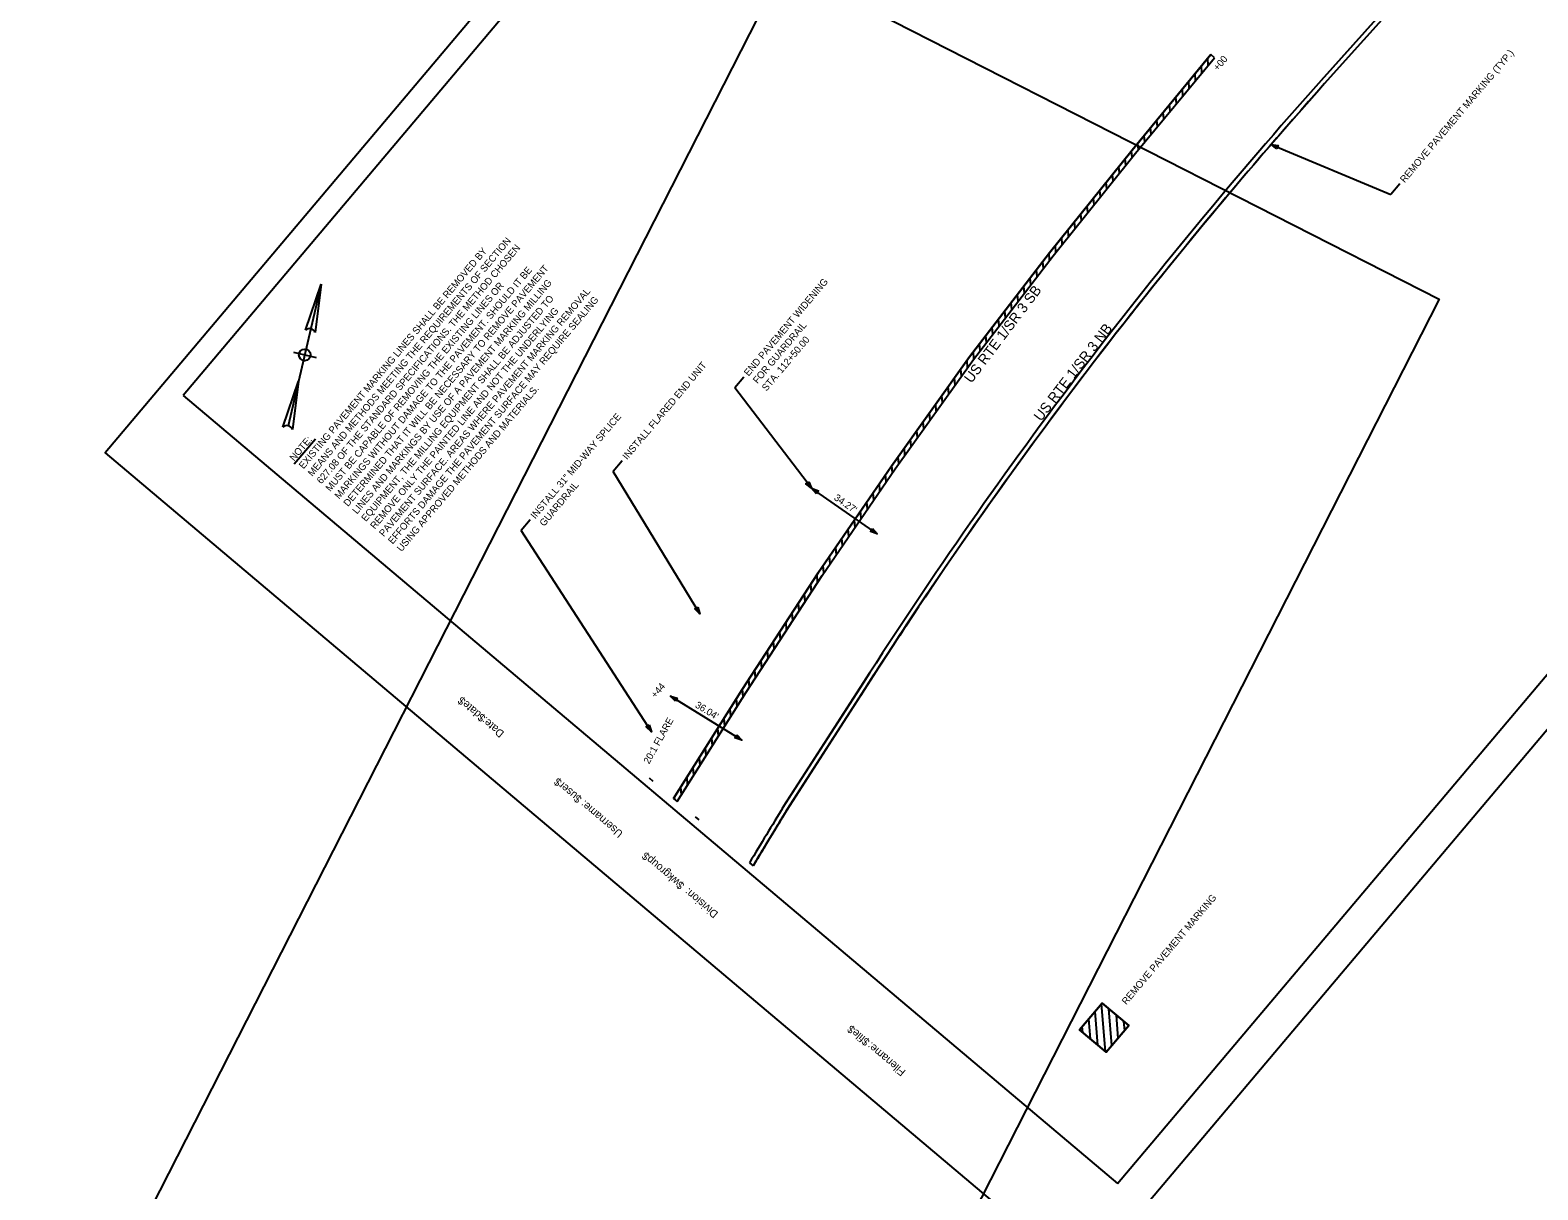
# Model space of a CAD drawing. Extents: x 1667331 to 1668332, y 338257 to 339476.
# Drawn here: x 1667331 to 1667979, y 338510 to 339008 of the extents above; entities that cross this region are included whole.
import ezdxf

# ---------------------------------------------------------------- set-up
doc = ezdxf.new("R2010")
doc.units = 0
for name, color, linetype in [('ANNOTATION', 7, 'Continuous'), ('BORDER', 7, 'Continuous'), ('CLIPS', 7, 'Continuous'), ('DIMENSIONS', 7, 'Continuous'), ('H_V CONTROLS', 7, 'Continuous'), ('PATTERNING', 7, 'Continuous'), ('PLOT BOUNDARY', 7, 'Continuous'), ('SHADING', 7, 'Continuous')]:
    doc.layers.add(name, color=color, linetype=linetype)

msp = doc.modelspace()

# ---------------------------------------------------------------- linework, layer by layer
at = {"layer": 'ANNOTATION'}
for p, q in [((1667864.55, 338958.88), (1667915.92, 338937.4)), ((1667919.79, 338941.99), (1667915.92, 338937.4)), ((1667919.79, 338941.99), (1667915.92, 338937.4)), ((1667919.79, 338941.99), (1667915.92, 338937.4)), ((1667637.98, 338858.92), (1667634.12, 338854.33)), ((1667667.17, 338811.15), (1667634.12, 338854.33)), ((1667444.93, 338821.68), (1667454.01, 338832.44)), ((1667585.82, 338823.01), (1667581.95, 338818.43)), ((1667619.21, 338757.17), (1667581.95, 338818.43)), ((1667546.32, 338797.61), (1667542.45, 338793.02)), ((1667598.39, 338706.56), (1667542.45, 338793.02))]:
    msp.add_line(p, q, dxfattribs=at)
for points in [[(1667867.03, 338957.03), (1667864.55, 338958.88), (1667867.61, 338958.41)], [(1667665.94, 338813.99), (1667667.17, 338811.15), (1667664.75, 338813.08)], [(1667665.94, 338813.99), (1667667.17, 338811.15), (1667664.75, 338813.08)], [(1667618.3, 338760.12), (1667619.21, 338757.17), (1667617.01, 338759.34)], [(1667597.39, 338709.48), (1667598.39, 338706.56), (1667596.13, 338708.67)]]:
    msp.add_lwpolyline(points, close=True, dxfattribs=at)
at = {"layer": 'BORDER'}
for p, q in [((1667913.08, 339462.54), (1667397.25, 338851.05)), ((1667798.54, 338512.53), (1668314.37, 339124.02)), ((1667397.25, 338851.05), (1667798.54, 338512.53))]:
    msp.add_line(p, q, dxfattribs=at)
at = {"layer": 'CLIPS'}
msp.add_lwpolyline([(1667331.49, 338399.89), (1667655.46, 339035.73), (1667936.78, 338892.39), (1667612.81, 338256.55)], close=True, dxfattribs=at)
at = {"layer": 'DIMENSIONS'}
for p, q in [((1667695.29, 338791.56), (1667667.17, 338811.15)), ((1667695.29, 338791.56), (1667667.17, 338811.15)), ((1667637.16, 338702.99), (1667606.49, 338721.92))]:
    msp.add_line(p, q, dxfattribs=at)
for points in [[(1667669.2, 338808.82), (1667667.17, 338811.15), (1667670.06, 338810.05)], [(1667669.2, 338808.82), (1667667.17, 338811.15), (1667670.06, 338810.05)], [(1667693.25, 338793.89), (1667695.29, 338791.56), (1667692.4, 338792.66)], [(1667693.25, 338793.89), (1667695.29, 338791.56), (1667692.4, 338792.66)], [(1667608.64, 338719.71), (1667606.49, 338721.92), (1667609.43, 338720.98)], [(1667635, 338705.2), (1667637.16, 338702.99), (1667634.21, 338703.93)]]:
    msp.add_lwpolyline(points, close=True, dxfattribs=at)
at = {"layer": 'H_V CONTROLS'}
for p, q in [((1667456.56, 338898.91), (1667442.34, 338838.05)), ((1667449.79, 338879.09), (1667456.56, 338898.91)), ((1667456.56, 338898.91), (1667453.85, 338878.15)), ((1667444.58, 338869.61), (1667454.32, 338867.34)), ((1667440.06, 338837.43), (1667446.82, 338857.24)), ((1667446.82, 338857.24), (1667444.11, 338836.48))]:
    msp.add_line(p, q, dxfattribs=at)
msp.add_circle((1667449.45, 338868.48), 2.5, dxfattribs=at)
for centre in [(1667451.5, 338877.27), (1667441.77, 338835.61)]:
    msp.add_arc(centre, 2.5, 20.40685, 133.29223, dxfattribs=at)
at = {"layer": 'PATTERNING'}
for p, q in [((1667886.05, 338986.32), (1667928.43, 339033.64)), ((1667928.43, 339033.64), (1667886.05, 338986.32)), ((1667887.54, 338984.99), (1667929.92, 339032.31)), ((1667887.54, 338984.99), (1667929.92, 339032.31)), ((1667834.84, 338989.65), (1667834.6, 338992.49)), ((1667837.57, 338992.95), (1667837.33, 338995.8)), ((1667840.21, 338996.14), (1667838.69, 338997.45)), ((1667829.38, 338983.04), (1667829.14, 338985.89)), ((1667832.11, 338986.34), (1667831.87, 338989.19)), ((1667823.92, 338976.43), (1667823.68, 338979.28)), ((1667826.65, 338979.74), (1667826.41, 338982.58)), ((1667818.46, 338969.83), (1667818.22, 338972.68)), ((1667821.19, 338973.13), (1667820.95, 338975.98)), ((1667813, 338963.22), (1667812.75, 338966.07)), ((1667815.73, 338966.53), (1667815.49, 338969.37)), ((1667807.54, 338956.62), (1667807.29, 338959.46)), ((1667810.27, 338959.92), (1667810.02, 338962.77)), ((1667802.09, 338949.88), (1667801.84, 338952.77)), ((1667804.81, 338953.27), (1667804.56, 338956.15)), ((1667799.36, 338946.5), (1667799.12, 338949.38)), ((1667793.91, 338939.73), (1667793.67, 338942.61)), ((1667796.64, 338943.11), (1667796.39, 338946)), ((1667788.47, 338932.95), (1667788.22, 338935.84)), ((1667791.19, 338936.34), (1667790.95, 338939.23)), ((1667783.02, 338926.18), (1667782.78, 338929.07)), ((1667785.74, 338929.57), (1667785.5, 338932.46)), ((1667777.57, 338919.41), (1667777.33, 338922.3)), ((1667780.3, 338922.8), (1667780.05, 338925.68)), ((1667772.13, 338912.64), (1667771.88, 338915.53)), ((1667774.85, 338916.03), (1667774.61, 338918.91)), ((1667766.7, 338905.64), (1667766.45, 338908.6)), ((1667769.41, 338909.18), (1667769.16, 338912.14)), ((1667761.28, 338898.57), (1667761.03, 338901.53)), ((1667763.99, 338902.11), (1667763.74, 338905.07)), ((1667755.86, 338891.51), (1667755.6, 338894.46)), ((1667758.57, 338895.04), (1667758.32, 338898)), ((1667753.14, 338887.97), (1667752.89, 338890.93)), ((1667747.72, 338880.9), (1667747.47, 338883.86)), ((1667750.43, 338884.44), (1667750.18, 338887.4)), ((1667742.3, 338873.84), (1667742.05, 338876.79)), ((1667745.01, 338877.37), (1667744.76, 338880.33)), ((1667736.88, 338866.77), (1667736.63, 338869.73)), ((1667739.59, 338870.3), (1667739.34, 338873.26)), ((1667731.49, 338859.27), (1667731.23, 338862.34)), ((1667734.19, 338863.03), (1667733.93, 338866.1)), ((1667728.8, 338855.51), (1667728.54, 338858.58)), ((1667723.42, 338847.99), (1667723.16, 338851.06)), ((1667726.11, 338851.75), (1667725.85, 338854.82)), ((1667718.04, 338840.47), (1667717.78, 338843.54)), ((1667720.73, 338844.23), (1667720.47, 338847.3)), ((1667712.65, 338832.95), (1667712.39, 338836.02)), ((1667715.34, 338836.71), (1667715.08, 338839.78)), ((1667709.96, 338829.19), (1667709.7, 338832.26)), ((1667704.58, 338821.67), (1667704.32, 338824.74)), ((1667707.27, 338825.43), (1667707.01, 338828.5)), ((1667699.21, 338813.93), (1667698.94, 338817.08)), ((1667701.89, 338817.84), (1667701.62, 338820.98)), ((1667696.53, 338810.01), (1667696.27, 338813.16)), ((1667691.18, 338802.19), (1667690.91, 338805.34)), ((1667693.85, 338806.1), (1667693.59, 338809.25)), ((1667685.82, 338794.36), (1667685.55, 338797.51)), ((1667688.5, 338798.28), (1667688.23, 338801.43)), ((1667683.14, 338790.45), (1667682.87, 338793.6)), ((1667677.78, 338782.63), (1667677.51, 338785.78)), ((1667680.46, 338786.54), (1667680.19, 338789.69)), ((1667672.42, 338774.8), (1667672.16, 338777.95)), ((1667675.1, 338778.71), (1667674.84, 338781.86)), ((1667669.76, 338770.76), (1667669.48, 338774)), ((1667664.43, 338762.58), (1667664.15, 338765.82)), ((1667667.09, 338766.67), (1667666.82, 338769.91)), ((1667661.77, 338758.49), (1667661.49, 338761.73)), ((1667656.44, 338750.31), (1667656.16, 338753.55)), ((1667659.1, 338754.4), (1667658.83, 338757.64)), ((1667651.11, 338742.13), (1667650.84, 338745.37)), ((1667653.77, 338746.22), (1667653.5, 338749.46)), ((1667648.45, 338738.04), (1667648.17, 338741.28)), ((1667643.12, 338729.86), (1667642.84, 338733.1)), ((1667645.78, 338733.95), (1667645.51, 338737.19)), ((1667640.46, 338725.77), (1667640.18, 338729.01)), ((1667692.22, 338732.05), (1667654.56, 338673.59)), ((1667693.9, 338730.97), (1667656.24, 338672.5)), ((1667635.14, 338717.41), (1667634.86, 338720.71)), ((1667637.8, 338721.62), (1667637.52, 338724.92)), ((1667686.43, 338723.07), (1667655, 338674.27)), ((1667632.49, 338713.19), (1667632.21, 338716.5)), ((1667627.18, 338704.77), (1667626.9, 338708.08)), ((1667629.84, 338708.98), (1667629.56, 338712.29)), ((1667624.53, 338700.56), (1667624.25, 338703.86)), ((1667619.22, 338692.13), (1667618.94, 338695.44)), ((1667621.88, 338696.34), (1667621.6, 338699.65)), ((1667616.57, 338687.92), (1667616.29, 338691.23)), ((1667597.39, 338686.71), (1667598.93, 338685.4)), ((1667611.26, 338679.5), (1667610.98, 338682.8)), ((1667613.92, 338683.71), (1667613.64, 338687.01)), ((1667607.87, 338677.86), (1667609.41, 338676.56)), ((1667608.43, 338677.38), (1667608.33, 338678.59)), ((1667617.14, 338670.03), (1667618.69, 338668.73)), ((1667656.24, 338672.5), (1667656.7, 338673.21)), ((1667640.5, 338650.31), (1667642.05, 338649)), ((1667640.5, 338650.31), (1667642.05, 338649)), ((1667790.14, 338571.95), (1667788.91, 338586.42)), ((1667793.38, 338569.21), (1667791.65, 338589.67)), ((1667796.18, 338571.77), (1667794.83, 338587.61)), ((1667798.91, 338575.01), (1667798.07, 338584.88)), ((1667783.65, 338577.42), (1667783.44, 338579.94)), ((1667786.9, 338574.68), (1667786.18, 338583.18)), ((1667801.65, 338578.26), (1667801.32, 338582.14))]:
    msp.add_line(p, q, dxfattribs=at)
for points in [[(1667607.87, 338677.86), (1667637.37, 338724.69), (1667669.99, 338774.78), (1667701.41, 338820.68), (1667735.04, 338867.66), (1667769.3, 338912.32), (1667804.8, 338956.44), (1667838.69, 338997.45)], [(1667609.41, 338676.56), (1667639.05, 338723.61), (1667671.65, 338773.67), (1667703.05, 338819.53), (1667736.65, 338866.46), (1667770.87, 338911.08), (1667806.35, 338955.18), (1667840.21, 338996.14)], [(1667656.7, 338673.22), (1667688.12, 338721.99), (1667693.9, 338730.97)], [(1667686.45, 338723.05), (1667686.43, 338723.07)], [(1667655, 338674.27), (1667655, 338674.27)], [(1667656.26, 338672.49), (1667656.24, 338672.5)], [(1667656.7, 338673.22), (1667656.7, 338673.22)]]:
    msp.add_lwpolyline(points, dxfattribs=at)
msp.add_lwpolyline([(1667782.29, 338578.57), (1667791.96, 338590.04), (1667803.43, 338580.37), (1667793.75, 338568.9)], close=True, dxfattribs=at)
for centre, radius, start, end in [((1669392.96, 337636.6), 2023, 138.14955, 147.51698), ((1669392.96, 337636.6), 2023, 138.14955, 147.51698), ((1669392.96, 337636.6), 2021, 138.14955, 147.51698), ((1669392.96, 337636.6), 2021, 138.14955, 147.21431), ((1669776.12, 337374.41), 2487.73, 148.49935, 149.14429), ((1669776.12, 337374.41), 2487.73, 148.49935, 149.14429), ((1669776.12, 337374.41), 2485.73, 148.49935, 149.15186), ((1669776.12, 337374.41), 2485.73, 148.51901, 149.15186), ((1669776.12, 337374.41), 2485.73, 148.49935, 148.49961)]:
    msp.add_arc(centre, radius, start, end, dxfattribs=at)
at = {"layer": 'PLOT BOUNDARY'}
msp.add_lwpolyline([(1667784.14, 338471.74), (1668332.21, 339121.45), (1667911.81, 339476.08), (1667363.74, 338826.37)], close=True, dxfattribs=at)
at = {"layer": 'SHADING'}
for p, q in [((1667928.43, 339033.64), (1667886.05, 338986.32)), ((1667887.54, 338984.99), (1667929.92, 339032.31)), ((1667840.21, 338996.14), (1667838.69, 338997.45)), ((1667686.45, 338723.05), (1667655, 338674.27)), ((1667607.87, 338677.86), (1667609.41, 338676.56)), ((1667656.26, 338672.49), (1667656.7, 338673.21)), ((1667656.7, 338673.22), (1667656.7, 338673.22)), ((1667640.5, 338650.31), (1667642.05, 338649))]:
    msp.add_line(p, q, dxfattribs=at)
for points in [[(1667838.69, 338997.45), (1667804.8, 338956.44), (1667769.3, 338912.32), (1667735.04, 338867.66), (1667701.41, 338820.68), (1667669.99, 338774.78), (1667637.37, 338724.69), (1667607.87, 338677.86)], [(1667609.41, 338676.56), (1667639.05, 338723.61), (1667671.65, 338773.67), (1667703.05, 338819.53), (1667736.65, 338866.46), (1667770.87, 338911.08), (1667806.35, 338955.18), (1667840.21, 338996.14)], [(1667656.7, 338673.22), (1667688.12, 338721.99), (1667693.9, 338730.97)], [(1667793.75, 338568.9), (1667803.43, 338580.37), (1667791.96, 338590.04), (1667782.29, 338578.57), (1667793.75, 338568.9)]]:
    msp.add_lwpolyline(points, dxfattribs=at)
for centre, radius, start, end in [((1669392.96, 337636.6), 2023, 138.14955, 147.51698), ((1669392.96, 337636.6), 2021, 138.14955, 147.21431), ((1669776.12, 337374.41), 2487.73, 148.49935, 149.14429), ((1669776.12, 337374.41), 2485.73, 148.51901, 149.15186), ((1669776.12, 337374.41), 2485.73, 148.49935, 148.49961)]:
    msp.add_arc(centre, radius, start, end, dxfattribs=at)

# ---------------------------------------------------------------- texts
at = {"layer": 'ANNOTATION'}
for s, height, rotation, p in [('REMOVE PAVEMENT MARKING (TYP.)', 3, 49.8502, (1667921.9, 338942.17)), ('REMOVE PAVEMENT MARKING (TYP.)', 3, 49.8502, (1667921.9, 338942.17)), ('REMOVE PAVEMENT MARKING (TYP.)', 3, 49.8502, (1667921.9, 338942.17)), ('+00', 3, 49.8502, (1667841.66, 338990.26)), ('EXISTING PAVEMENT MARKING LINES SHALL BE REMOVED BY ', 3, 49.8502, (1667448.9, 338819.24)), ('MEANS AND METHODS MEETING THE REQUIREMENTS OF SECTION ', 3, 49.8502, (1667452.73, 338816.01)), ('627.08 OF THE STANDARD SPECIFICATIONS. THE METHOD CHOSEN ', 3, 49.8502, (1667456.56, 338812.78)), ('DETERMINED THAT IT WILL BE NECESSARY TO REMOVE PAVEMENT ', 3, 49.8502, (1667468.05, 338803.09)), ('MARKINGS WITHOUT DAMAGE TO THE PAVEMENT. SHOULD IT BE ', 3, 49.8502, (1667464.22, 338806.32)), ('END PAVEMENT WIDENING', 3, 49.8502, (1667640.1, 338859.1)), ('MUST BE CAPABLE OF REMOVING THE EXISTING LINES OR ', 3, 49.8502, (1667460.39, 338809.55)), ('LINES AND MARKINGS BY USE OF A PAVEMENT MARKING MILLING ', 3, 49.8502, (1667471.88, 338799.86)), ('PAVEMENT SURFACE. AREAS WHERE PAVEMENT MARKING REMOVAL ', 3, 49.8502, (1667483.37, 338790.16)), ('US RTE 1/SR 3 SB', 4.375, 52.96159, (1667735.8, 338856.01)), ('EQUIPMENT, THE MILLING EQUIPMENT SHALL BE ADJUSTED TO ', 3, 49.8502, (1667475.71, 338796.63)), ('REMOVE ONLY THE PAINTED LINE AND NOT THE UNDERLYING ', 3, 49.8502, (1667479.54, 338793.4)), ('EFFORTS DAMAGE THE PAVEMENT SURFACE MAY REQUIRE SEALING ', 3, 49.8502, (1667487.2, 338786.93)), ('FOR GUARDRAIL', 3, 49.8502, (1667643.93, 338855.87)), ('US RTE 1/SR 3 NB', 4.375, 52.442, (1667765.69, 338839.63)), ('STA. 112+50.00', 3, 49.8502, (1667647.76, 338852.64)), ('INSTALL FLARED END UNIT', 3, 49.8502, (1667587.93, 338823.19)), ('USING APPROVED METHODS AND MATERIALS.', 3, 49.8502, (1667491.02, 338783.7)), ('INSTALL 31" MID-WAY SPLICE', 3, 49.8502, (1667548.43, 338797.78)), ('NOTE:', 3, 49.8502, (1667444.9, 338822.61)), ('GUARDRAIL', 3, 49.8502, (1667552.26, 338794.55)), ('+44', 3, 49.8502, (1667600.13, 338720.79)), ('20:1 FLARE', 3, 60.91032, (1667597.35, 338692.47)), ('REMOVE PAVEMENT MARKING', 3, 49.8502, (1667802.36, 338589.06))]:
    msp.add_text(s, height=height, rotation=rotation, dxfattribs=at).set_placement(p)
at = {"layer": 'BORDER'}
for s, p in [('$date$', (1667527.4, 338713.03)), ('Date:', (1667535.38, 338706.3)), ('$user$', (1667568.72, 338678.17)), ('Username:', (1667586.4, 338663.26)), ('$wkgroup$', (1667612.76, 338641.02)), ('Division:', (1667627.3, 338628.76)), ('$file$', (1667692.42, 338573.82)), ('Filename:', (1667707.81, 338560.84))]:
    msp.add_text(s, height=3.348, rotation=139.8502, dxfattribs=at).set_placement(p)
at = {"layer": 'DIMENSIONS'}
for s, rotation, p in [("34.27'", 325.1254, (1667676.5, 338806.48)), ("34.27'", 325.1254, (1667676.5, 338806.48)), ("36.04'", 328.32044, (1667616.84, 338717.29))]:
    msp.add_text(s, height=3, rotation=rotation, dxfattribs=at).set_placement(p)

doc.saveas('drawing.dxf')
